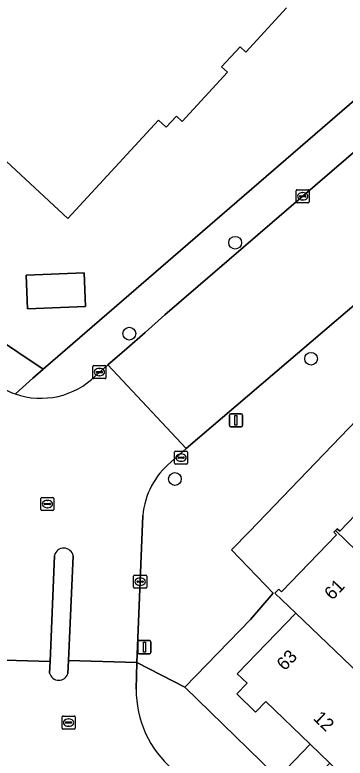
# Model space of a CAD drawing. Extents: x 159217 to 160349, y 381246 to 382172.
# Drawn here: x 159939 to 159964.4, y 381824.3 to 381881.2 of the extents above; entities that cross this region are included whole.
import ezdxf

# ---------------------------------------------------------------- set-up
doc = ezdxf.new("R2010")
doc.units = 0
for name, color, linetype in [('IMGEO_Boom', 7, 'Continuous'), ('IMGEO_Erf', 7, 'Continuous'), ('IMGEO_Kolk', 7, 'Continuous'), ('IMGEO_Lichtmast', 7, 'Continuous'), ('IMGEO_Pand', 7, 'Continuous'), ('IMGEO_Pand_nummerreeks', 7, 'Continuous'), ('IMGEO_Rijbaan_lokaal_gesloten', 7, 'Continuous'), ('IMGEO_Rijbaan_lokaal_open', 7, 'Continuous'), ('IMGEO_Rioolput', 7, 'Continuous'), ('IMGEO_Verkeerseiland_open', 7, 'Continuous'), ('IMGEO_Voetpad_open', 7, 'Continuous')]:
    doc.layers.add(name, color=color, linetype=linetype)

msp = doc.modelspace()

# ---------------------------------------------------------------- linework, layer by layer
at = {"layer": 'IMGEO_Boom'}
for centre in [(159955.913, 381863.761), (159947.791, 381856.795), (159961.738, 381854.873), (159951.292, 381845.657)]:
    msp.add_circle(centre, 0.489, dxfattribs=at)
at = {"layer": 'IMGEO_Erf'}
for points in [[(159887.833, 381889.831), (159941.192, 381854.075), (159947.76, 381859.745), (159951.731, 381863.172), (160032.516, 381932.902)], [(159959.858, 381881.752), (159956.727, 381878.355), (159956.286, 381878.762), (159954.877, 381877.232), (159955.318, 381876.825), (159951.848, 381873.06), (159951.408, 381873.467), (159950.619, 381872.611), (159950.03, 381873.153), (159943.083, 381865.615), (159937.627, 381870.643), (159937.22, 381870.201), (159933.456, 381873.672), (159933.863, 381874.114), (159932.326, 381875.53), (159931.919, 381875.088), (159928.162, 381878.552), (159928.569, 381878.994), (159927.024, 381880.417), (159926.617, 381879.975), (159922.86, 381883.438)], [(159959.214, 381822.777), (159961.679, 381825.334), (159958.278, 381828.612), (159957.486, 381827.79), (159956.04, 381829.185), (159956.828, 381830.002), (159956.07, 381830.733), (159960.556, 381835.383), (159958.968, 381836.914), (159959.264, 381837.221), (159959.477, 381837.016), (159963.692, 381841.385), (159963.49, 381841.579), (159963.616, 381841.71), (159963.741, 381841.839), (159963.938, 381841.649), (159968.15, 381846.014)]]:
    msp.add_lwpolyline(points, dxfattribs=at)
for points in [[(159994.561, 381838.781), (159999.055, 381843.386), (160001.857, 381846.257), (160004.708, 381843.475), (160014.315, 381853.212), (159990.64, 381876.569), (159957.007, 381841.635), (159955.642, 381840.217), (159958.818, 381836.919), (159957.077, 381834.899), (159952.057, 381829.709), (159972.505, 381809.81), (159974.918, 381812.289), (159970.479, 381816.617), (159974.953, 381821.209), (159979.393, 381816.882), (159984.048, 381822.097), (159980.266, 381818.215), (159978.214, 381820.214), (159981.998, 381824.097), (159981.093, 381824.98), (159985.545, 381829.543), (159990.058, 381834.167)], [(159944.439, 381858.885), (159939.979, 381858.7), (159939.873, 381861.266), (159944.333, 381861.45)]]:
    msp.add_lwpolyline(points, close=True, dxfattribs=at)
at = {"layer": 'IMGEO_Kolk'}
for p, q in [((159960.596, 381866.898), (159960.596, 381867.75)), ((159960.671, 381867.824), (159961.523, 381867.824)), ((159961.597, 381867.75), (159961.597, 381866.898)), ((159960.855, 381867.318), (159960.855, 381867.33)), ((159961.293, 381867.281), (159960.895, 381867.281)), ((159960.898, 381867.367), (159961.296, 381867.367)), ((159961.084, 381867.604), (159961.109, 381867.604)), ((159961.339, 381867.33), (159961.339, 381867.318)), ((159961.523, 381866.824), (159960.671, 381866.824)), ((159961.107, 381867.044), (159961.082, 381867.044)), ((159944.998, 381853.419), (159944.998, 381854.271)), ((159945.073, 381854.345), (159945.925, 381854.345)), ((159945.486, 381854.125), (159945.511, 381854.125)), ((159945.999, 381854.271), (159945.999, 381853.419)), ((159945.257, 381853.839), (159945.257, 381853.851)), ((159945.695, 381853.802), (159945.297, 381853.802)), ((159945.3, 381853.888), (159945.698, 381853.888)), ((159945.509, 381853.565), (159945.484, 381853.565)), ((159945.741, 381853.851), (159945.741, 381853.839)), ((159945.925, 381853.345), (159945.073, 381853.345)), ((159951.337, 381847.797), (159952.189, 381847.797)), ((159951.262, 381846.871), (159951.262, 381847.723)), ((159951.521, 381847.291), (159951.521, 381847.303)), ((159951.959, 381847.254), (159951.561, 381847.254)), ((159951.564, 381847.34), (159951.962, 381847.34)), ((159951.75, 381847.577), (159951.775, 381847.577)), ((159952.005, 381847.303), (159952.005, 381847.291)), ((159952.263, 381847.723), (159952.263, 381846.871)), ((159952.189, 381846.797), (159951.337, 381846.797)), ((159951.773, 381847.017), (159951.748, 381847.017)), ((159948.123, 381837.358), (159948.123, 381838.21)), ((159948.198, 381838.284), (159949.05, 381838.284)), ((159949.124, 381838.21), (159949.124, 381837.358)), ((159948.382, 381837.778), (159948.382, 381837.79)), ((159948.82, 381837.741), (159948.422, 381837.741)), ((159948.425, 381837.827), (159948.823, 381837.827)), ((159948.611, 381838.064), (159948.636, 381838.064)), ((159948.866, 381837.79), (159948.866, 381837.778)), ((159949.05, 381837.284), (159948.198, 381837.284)), ((159948.634, 381837.504), (159948.609, 381837.504))]:
    msp.add_line(p, q, dxfattribs=at)
for points in [[(159960.596, 381866.898), (159960.596, 381867.75)], [(159960.671, 381867.824), (159961.523, 381867.824)], [(159961.597, 381867.75), (159961.597, 381866.898)], [(159961.523, 381866.824), (159960.671, 381866.824)], [(159944.998, 381853.419), (159944.998, 381854.271)], [(159945.073, 381854.345), (159945.925, 381854.345)], [(159945.999, 381854.271), (159945.999, 381853.419)], [(159945.925, 381853.345), (159945.073, 381853.345)], [(159951.337, 381847.797), (159952.189, 381847.797)], [(159951.262, 381846.871), (159951.262, 381847.723)], [(159952.263, 381847.723), (159952.263, 381846.871)], [(159952.189, 381846.797), (159951.337, 381846.797)], [(159948.123, 381837.358), (159948.123, 381838.21)], [(159948.198, 381838.284), (159949.05, 381838.284)], [(159949.124, 381838.21), (159949.124, 381837.358)], [(159949.05, 381837.284), (159948.198, 381837.284)]]:
    msp.add_lwpolyline(points, dxfattribs=at)
for centre, radius, start, end in [((159960.673, 381867.748), 0.0765, 91.552, 178.448), ((159960.673, 381867.748), 0.0765, 91.552, 178.448), ((159961.521, 381867.748), 0.0765, 1.552, 88.448), ((159961.521, 381867.748), 0.0765, 1.552, 88.448), ((159960.895, 381867.327), 0.0403, 85.8775, 175.7526), ((159960.892, 381867.317), 0.0366, 178.938, 274.7102), ((159961.296, 381867.324), 0.043, 264.8664, 352.4533), ((159961.3, 381867.329), 0.0386, 1.7309, 96.639), ((159960.673, 381866.9), 0.0765, 181.552, 268.448), ((159960.673, 381866.9), 0.0765, 181.552, 268.448), ((159961.521, 381866.9), 0.0765, 271.552, 358.448), ((159961.521, 381866.9), 0.0765, 271.552, 358.448), ((159945.075, 381854.269), 0.0765, 91.552, 178.448), ((159945.075, 381854.269), 0.0765, 91.552, 178.448), ((159945.923, 381854.269), 0.0765, 1.552, 88.448), ((159945.923, 381854.269), 0.0765, 1.552, 88.448), ((159945.297, 381853.848), 0.0403, 85.8775, 175.7526), ((159945.294, 381853.838), 0.0366, 178.938, 274.7102), ((159945.698, 381853.845), 0.043, 264.8664, 352.4533), ((159945.702, 381853.85), 0.0386, 1.7309, 96.639), ((159945.075, 381853.421), 0.0765, 181.552, 268.448), ((159945.075, 381853.421), 0.0765, 181.552, 268.448), ((159945.923, 381853.421), 0.0765, 271.552, 358.448), ((159945.923, 381853.421), 0.0765, 271.552, 358.448), ((159951.339, 381847.721), 0.0765, 91.552, 178.448), ((159951.339, 381847.721), 0.0765, 91.552, 178.448), ((159952.187, 381847.721), 0.0765, 1.552, 88.448), ((159952.187, 381847.721), 0.0765, 1.552, 88.448), ((159951.561, 381847.3), 0.0403, 85.8775, 175.7526), ((159951.558, 381847.29), 0.0366, 178.938, 274.7102), ((159951.962, 381847.297), 0.043, 264.8664, 352.4533), ((159951.966, 381847.302), 0.0386, 1.7309, 96.639), ((159951.339, 381846.873), 0.0765, 181.552, 268.448), ((159951.339, 381846.873), 0.0765, 181.552, 268.448), ((159952.187, 381846.873), 0.0765, 271.552, 358.448), ((159952.187, 381846.873), 0.0765, 271.552, 358.448), ((159948.2, 381838.208), 0.0765, 91.552, 178.448), ((159948.2, 381838.208), 0.0765, 91.552, 178.448), ((159949.048, 381838.208), 0.0765, 1.552, 88.448), ((159949.048, 381838.208), 0.0765, 1.552, 88.448), ((159948.422, 381837.787), 0.0403, 85.8775, 175.7526), ((159948.419, 381837.777), 0.0366, 178.938, 274.7102), ((159948.823, 381837.784), 0.043, 264.8664, 352.4533), ((159948.827, 381837.789), 0.0386, 1.7309, 96.639), ((159948.2, 381837.36), 0.0765, 181.552, 268.448), ((159948.2, 381837.36), 0.0765, 181.552, 268.448), ((159949.048, 381837.36), 0.0765, 271.552, 358.448), ((159949.048, 381837.36), 0.0765, 271.552, 358.448)]:
    msp.add_arc(centre, radius, start, end, dxfattribs=at)
for centre, major_axis, ratio, start_param, end_param in [((159961.083, 381867.324), (-0.387, 0.002), 0.722429, 4.712389, 7.853982), ((159961.108, 381867.324), (-0.39, 0.002), 0.717154, 1.570796, 4.712389), ((159945.485, 381853.845), (-0.387, 0.002), 0.722429, 4.712389, 7.853982), ((159945.51, 381853.845), (-0.39, 0.002), 0.717154, 1.570796, 4.712389), ((159951.749, 381847.297), (-0.387, 0.002), 0.722429, 4.712389, 7.853982), ((159951.774, 381847.297), (-0.39, 0.002), 0.717154, 1.570796, 4.712389), ((159948.61, 381837.784), (-0.387, 0.002), 0.722429, 4.712389, 7.853982), ((159948.635, 381837.784), (-0.39, 0.002), 0.717154, 1.570796, 4.712389)]:
    msp.add_ellipse(centre, major_axis=major_axis, ratio=ratio, start_param=start_param, end_param=end_param, dxfattribs=at)
at = {"layer": 'IMGEO_Lichtmast'}
for p, q in [((159955.577, 381850.644), (159956.367, 381850.644)), ((159956.367, 381850.644), (159955.577, 381850.644)), ((159955.477, 381849.744), (159955.477, 381850.544)), ((159955.477, 381850.544), (159955.477, 381849.744)), ((159956.467, 381850.544), (159956.467, 381849.744)), ((159956.467, 381849.744), (159956.467, 381850.544)), ((159956.367, 381849.644), (159955.577, 381849.644)), ((159955.577, 381849.644), (159956.367, 381849.644)), ((159948.454, 381832.37), (159948.454, 381833.17)), ((159948.454, 381833.17), (159948.454, 381832.37)), ((159948.554, 381833.27), (159949.344, 381833.27)), ((159949.344, 381833.27), (159948.554, 381833.27)), ((159949.444, 381833.17), (159949.444, 381832.37)), ((159949.444, 381832.37), (159949.444, 381833.17)), ((159949.344, 381832.27), (159948.554, 381832.27)), ((159948.554, 381832.27), (159949.344, 381832.27))]:
    msp.add_line(p, q, dxfattribs=at)
for points in [[(159955.897, 381850.519), (159956.047, 381850.519), (159956.047, 381849.769), (159955.897, 381849.769), (159955.897, 381850.519)], [(159948.874, 381833.145), (159949.024, 381833.145), (159949.024, 381832.395), (159948.874, 381832.395), (159948.874, 381833.145)]]:
    msp.add_lwpolyline(points, dxfattribs=at)
for centre, start, end in [((159955.577, 381850.544), 90, 180), ((159955.577, 381850.544), 90, 180), ((159956.367, 381850.544), 0, 90), ((159956.367, 381850.544), 360, 90), ((159955.577, 381849.744), 180, 270), ((159955.577, 381849.744), 180, 270), ((159956.367, 381849.744), 270, 0), ((159956.367, 381849.744), 270, 0), ((159948.554, 381833.17), 90, 180), ((159948.554, 381833.17), 90, 180), ((159949.344, 381833.17), 0, 90), ((159949.344, 381833.17), 360, 90), ((159948.554, 381832.37), 180, 270), ((159948.554, 381832.37), 180, 270), ((159949.344, 381832.37), 270, 0), ((159949.344, 381832.37), 270, 0)]:
    msp.add_arc(centre, 0.1, start, end, dxfattribs=at)
at = {"layer": 'IMGEO_Pand'}
msp.add_lwpolyline([(159922.86, 381883.438), (159926.617, 381879.975), (159927.024, 381880.417), (159928.569, 381878.994), (159928.162, 381878.552), (159931.919, 381875.088), (159932.326, 381875.53), (159933.863, 381874.114), (159933.456, 381873.672), (159937.22, 381870.201), (159937.627, 381870.643), (159943.083, 381865.615), (159950.03, 381873.153), (159950.619, 381872.611), (159951.408, 381873.467), (159951.848, 381873.06), (159955.318, 381876.825), (159954.877, 381877.232), (159956.286, 381878.762), (159956.727, 381878.355), (159959.858, 381881.752)], dxfattribs=at)
for points in [[(159944.439, 381858.885), (159944.333, 381861.45), (159939.873, 381861.266), (159939.979, 381858.7)], [(159968.038, 381846.334), (159967.932, 381846.224), (159968.15, 381846.014), (159963.938, 381841.649), (159963.741, 381841.839), (159963.616, 381841.71), (159970.736, 381834.824), (159972.297, 381833.325), (159972.783, 381832.858), (159973.98, 381835.106), (159972.546, 381836.492), (159975.29, 381839.325), (159975.185, 381839.425)], [(159963.616, 381841.71), (159963.49, 381841.579), (159963.692, 381841.385), (159959.477, 381837.016), (159959.264, 381837.221), (159958.968, 381836.914), (159960.556, 381835.383), (159965.393, 381830.741), (159967.1, 381829.09), (159967.67, 381828.521), (159972.297, 381833.325), (159970.736, 381834.824)], [(159967.1, 381829.09), (159965.393, 381830.741), (159960.556, 381835.383), (159956.07, 381830.733), (159956.828, 381830.002), (159956.04, 381829.185), (159957.486, 381827.79), (159958.278, 381828.612), (159961.679, 381825.334), (159963.185, 381823.882), (159965.037, 381822.096), (159968.507, 381825.697), (159969.5, 381826.728), (159967.67, 381828.521)], [(159963.185, 381823.882), (159961.679, 381825.334), (159959.214, 381822.777), (159960.72, 381821.325)]]:
    msp.add_lwpolyline(points, close=True, dxfattribs=at)
at = {"layer": 'IMGEO_Rijbaan_lokaal_gesloten'}
for points in [[(159937.597, 381852.913), (159925.548, 381861.046), (159922.012, 381863.423), (159918.533, 381865.684), (159913.46, 381858.201), (159932.433, 381845.449), (159933.505, 381844.804), (159933.966, 381844.465), (159934.458, 381844.036), (159934.91, 381843.564), (159935.318, 381843.053), (159935.679, 381842.508), (159935.989, 381841.933), (159936.247, 381841.333), (159936.451, 381840.712), (159936.598, 381840.075), (159936.688, 381839.428), (159936.719, 381838.775), (159936.543, 381832.512), (159936.509, 381831.835), (159941.711, 381831.68), (159942.042, 381839.799)], [(159946.153, 381854.406), (159945.204, 381853.564)], [(159950.972, 381846.948), (159952.156, 381847.982), (159946.153, 381854.406)], [(159943.496, 381839.772), (159943.128, 381831.745), (159948.378, 381831.596), (159948.828, 381842.865)]]:
    msp.add_lwpolyline(points, dxfattribs=at)
for centre, radius, start, end in [((159941.008, 381857.815), 5.973, 250.8184, 314.6212), ((159941.007, 381857.81), 5.967, 235.1448, 250.8114), ((159954.818, 381842.324), 6.014, 129.7525, 174.8392), ((159942.766, 381839.609), 0.748, 12.5932, 165.2792)]:
    msp.add_arc(centre, radius, start, end, dxfattribs=at)
at = {"layer": 'IMGEO_Rijbaan_lokaal_open'}
msp.add_lwpolyline([(159982.838, 381874.211), (159977.026, 381881.069), (159976.51, 381880.603), (159971.031, 381875.869), (159954.349, 381861.525), (159950.517, 381858.23), (159949.004, 381856.893), (159947.613, 381855.663), (159946.153, 381854.406), (159952.156, 381847.982), (159972.211, 381865.09)], close=True, dxfattribs=at)
for points in [[(159941.675, 381830.784), (159941.711, 381831.68), (159936.509, 381831.835), (159936.272, 381827.161)], [(159948.318, 381829.552), (159948.378, 381831.596), (159943.128, 381831.745), (159943.083, 381830.754)]]:
    msp.add_lwpolyline(points, dxfattribs=at)
for centre, radius, start, end in [((159942.383, 381830.961), 0.73, 194.0059, 343.5528), ((159956.313, 381829.5), 7.996, 179.6258, 229.6535)]:
    msp.add_arc(centre, radius, start, end, dxfattribs=at)
at = {"layer": 'IMGEO_Rioolput'}
for p, q in [((159941.005, 381843.31), (159941.005, 381844.162)), ((159941.08, 381844.236), (159941.932, 381844.236)), ((159941.493, 381844.016), (159941.518, 381844.016)), ((159942.006, 381844.162), (159942.006, 381843.31)), ((159941.932, 381843.236), (159941.08, 381843.236)), ((159941.264, 381843.73), (159941.264, 381843.742)), ((159941.702, 381843.693), (159941.304, 381843.693)), ((159941.307, 381843.779), (159941.705, 381843.779)), ((159941.516, 381843.456), (159941.491, 381843.456)), ((159941.748, 381843.742), (159941.748, 381843.73)), ((159942.629, 381826.567), (159942.629, 381827.419)), ((159942.704, 381827.493), (159943.556, 381827.493)), ((159943.117, 381827.273), (159943.142, 381827.273)), ((159943.63, 381827.419), (159943.63, 381826.567)), ((159942.888, 381826.987), (159942.888, 381826.999)), ((159943.326, 381826.95), (159942.928, 381826.95)), ((159942.931, 381827.036), (159943.329, 381827.036)), ((159943.14, 381826.713), (159943.115, 381826.713)), ((159943.372, 381826.999), (159943.372, 381826.987)), ((159943.556, 381826.493), (159942.704, 381826.493))]:
    msp.add_line(p, q, dxfattribs=at)
for points in [[(159941.005, 381843.31), (159941.005, 381844.162)], [(159941.08, 381844.236), (159941.932, 381844.236)], [(159942.006, 381844.162), (159942.006, 381843.31)], [(159941.932, 381843.236), (159941.08, 381843.236)], [(159942.629, 381826.567), (159942.629, 381827.419)], [(159942.704, 381827.493), (159943.556, 381827.493)], [(159943.63, 381827.419), (159943.63, 381826.567)], [(159943.556, 381826.493), (159942.704, 381826.493)]]:
    msp.add_lwpolyline(points, dxfattribs=at)
for centre, radius, start, end in [((159941.082, 381844.16), 0.0765, 91.552, 178.448), ((159941.082, 381844.16), 0.0765, 91.552, 178.448), ((159941.93, 381844.16), 0.0765, 1.552, 88.448), ((159941.93, 381844.16), 0.0765, 1.552, 88.448), ((159941.082, 381843.312), 0.0765, 181.552, 268.448), ((159941.082, 381843.312), 0.0765, 181.552, 268.448), ((159941.304, 381843.739), 0.0403, 85.8775, 175.7526), ((159941.301, 381843.729), 0.0366, 178.938, 274.7102), ((159941.705, 381843.736), 0.043, 264.8664, 352.4533), ((159941.709, 381843.741), 0.0386, 1.7309, 96.639), ((159941.93, 381843.312), 0.0765, 271.552, 358.448), ((159941.93, 381843.312), 0.0765, 271.552, 358.448), ((159942.706, 381827.417), 0.0765, 91.552, 178.448), ((159942.706, 381827.417), 0.0765, 91.552, 178.448), ((159943.554, 381827.417), 0.0765, 1.552, 88.448), ((159943.554, 381827.417), 0.0765, 1.552, 88.448), ((159942.928, 381826.996), 0.0403, 85.8775, 175.7526), ((159942.925, 381826.986), 0.0366, 178.938, 274.7102), ((159943.329, 381826.993), 0.043, 264.8664, 352.4533), ((159943.333, 381826.998), 0.0386, 1.7309, 96.639), ((159942.706, 381826.569), 0.0765, 181.552, 268.448), ((159942.706, 381826.569), 0.0765, 181.552, 268.448), ((159943.554, 381826.569), 0.0765, 271.552, 358.448), ((159943.554, 381826.569), 0.0765, 271.552, 358.448)]:
    msp.add_arc(centre, radius, start, end, dxfattribs=at)
for centre, major_axis, ratio, start_param, end_param in [((159941.492, 381843.736), (-0.387, 0.002), 0.722429, 4.712389, 7.853982), ((159941.517, 381843.736), (-0.39, 0.002), 0.717154, 1.570796, 4.712389), ((159943.116, 381826.993), (-0.387, 0.002), 0.722429, 4.712389, 7.853982), ((159943.141, 381826.993), (-0.39, 0.002), 0.717154, 1.570796, 4.712389)]:
    msp.add_ellipse(centre, major_axis=major_axis, ratio=ratio, start_param=start_param, end_param=end_param, dxfattribs=at)
at = {"layer": 'IMGEO_Verkeerseiland_open'}
for points in [[(159942.042, 381839.799), (159941.711, 381831.68), (159941.675, 381830.784)], [(159943.083, 381830.754), (159943.128, 381831.745), (159943.496, 381839.772)]]:
    msp.add_lwpolyline(points, dxfattribs=at)
for centre, radius, start, end in [((159942.766, 381839.609), 0.748, 12.5932, 165.2792), ((159942.383, 381830.961), 0.73, 194.0059, 343.5528)]:
    msp.add_arc(centre, radius, start, end, dxfattribs=at)
at = {"layer": 'IMGEO_Voetpad_open'}
for points in [[(160076.575, 381973.183), (160073.471, 381969.337), (160070.179, 381965.651), (160069.798, 381966.001), (160066.708, 381962.801), (160050.259, 381948.217), (160047.054, 381945.45), (160035.937, 381935.855), (160032.516, 381932.902), (159951.731, 381863.172), (159947.76, 381859.745), (159941.192, 381854.075), (159940.376, 381853.371), (159939.046, 381852.174)], [(160065.438, 381945.337), (160012.675, 381899.899), (160000, 381888.954), (159998.229, 381887.404), (159993.21, 381883.114), (159982.838, 381874.211), (159972.211, 381865.09), (159952.156, 381847.982), (159950.972, 381846.948)], [(159948.828, 381842.865), (159948.378, 381831.596), (159952.057, 381829.709), (159957.077, 381834.899), (159958.818, 381836.919), (159955.642, 381840.217), (159957.007, 381841.635), (159990.64, 381876.569), (159990.482, 381876.75), (159992.495, 381878.483), (160000, 381884.944), (160033.475, 381913.761), (160034.634, 381914.758), (160067.439, 381942.998)], [(159945.204, 381853.564), (159946.153, 381854.406), (159947.613, 381855.663), (159949.004, 381856.893), (159950.517, 381858.23), (159954.349, 381861.525), (159971.031, 381875.869), (159976.51, 381880.603), (159977.026, 381881.069), (159987.216, 381889.848), (159992.095, 381893.974)], [(159939.046, 381852.174), (159940.376, 381853.371), (159941.192, 381854.075), (159887.833, 381889.831)], [(159995.728, 381787.091), (159989.764, 381792.975), (159986.539, 381796.132), (159983.209, 381799.393), (159973.639, 381808.707), (159972.505, 381809.81), (159952.057, 381829.709), (159948.378, 381831.596), (159948.318, 381829.552)]]:
    msp.add_lwpolyline(points, dxfattribs=at)
for centre, radius, start, end in [((159941.008, 381857.815), 5.973, 250.8184, 314.6212), ((159941.007, 381857.81), 5.967, 235.1448, 250.8114), ((159954.818, 381842.324), 6.014, 129.7525, 174.8392), ((159956.313, 381829.5), 7.996, 179.6258, 229.6535)]:
    msp.add_arc(centre, radius, start, end, dxfattribs=at)

# ---------------------------------------------------------------- texts
at = {"layer": 'IMGEO_Pand_nummerreeks'}
for s, rotation, p in [('61', 46.0272, (159963.364, 381836.32)), ('63', 46.0257, (159959.713, 381830.909)), ('12', 316.0484, (159961.84, 381827.261))]:
    msp.add_text(s, height=1, rotation=rotation, dxfattribs=at).set_placement(p)

doc.saveas('drawing.dxf')
